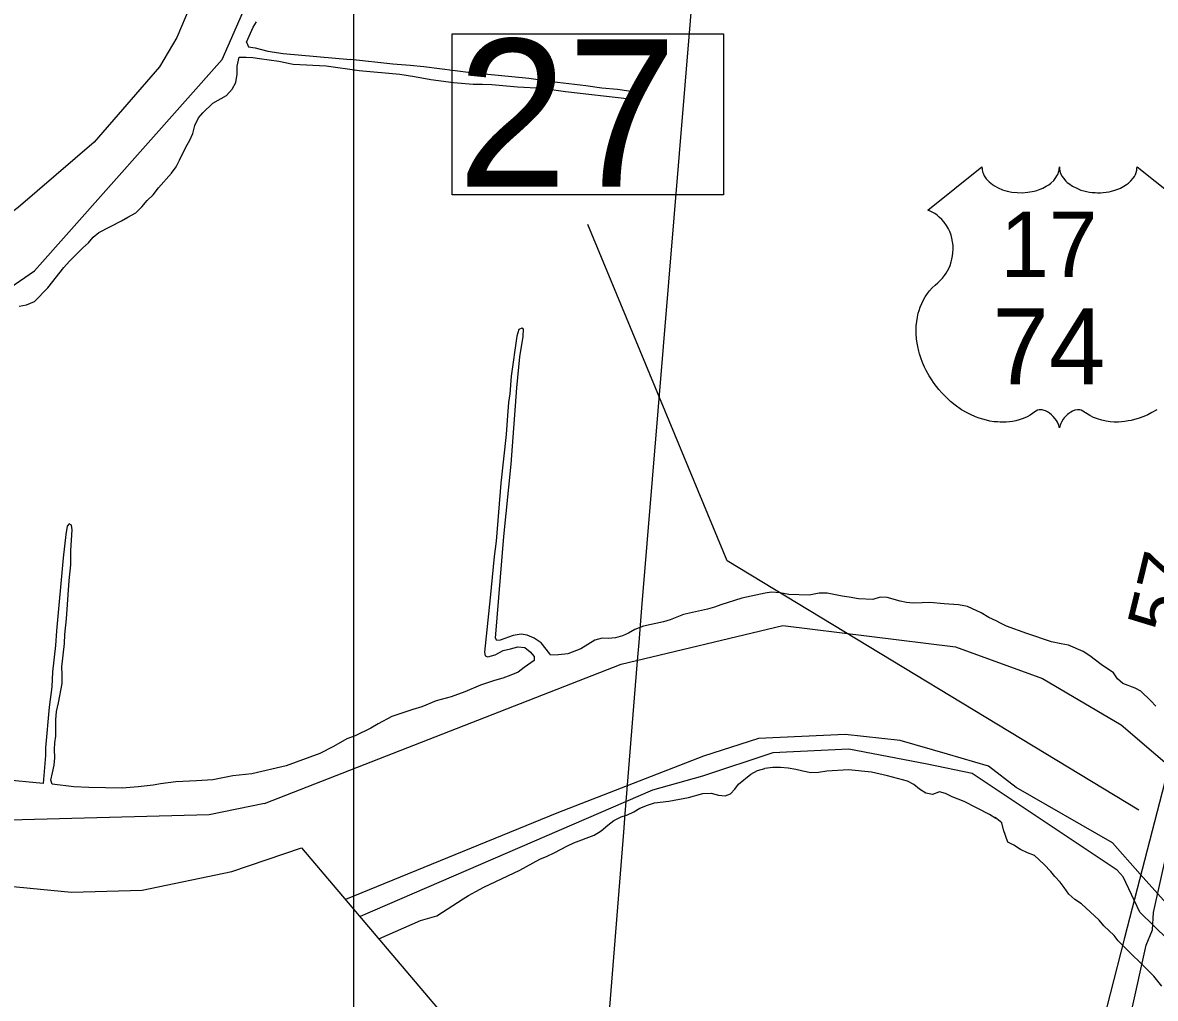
# Model space of a CAD drawing. Extents: x 2290055 to 2389491, y 66597 to 237875.
# Drawn here: x 2312342 to 2315029, y 180442 to 182758 of the extents above; entities that cross this region are included whole.
import ezdxf

# ---------------------------------------------------------------- set-up
doc = ezdxf.new("R2010")
doc.units = 0
for name, color, linetype in [('Exist Boundary Political CountyLine', 7, 'Continuous'), ('Exist Hydrographic Buffer Line', 7, 'Continuous'), ('Exist Hydrographic River Shore', 7, 'Continuous'), ('Exist Road Primary US Attributed', 7, 'Continuous'), ('Exist Road Primary US Mileage Hundredths English Label', 7, 'Continuous'), ('Exist Road Primary US Shield CELL', 7, 'Continuous'), ('Exist Road Primary US Shield Number Label', 7, 'Continuous'), ('Exist Road Primary US Structure Standard Bridge CELL', 7, 'Continuous'), ('Exist Road Primary US Structure Standard Bridge Number Label', 7, 'Continuous'), ('Exist Utilities Electrical Transmission Line', 7, 'Continuous'), ('Map Preparation Inset Cut Line', 7, 'Continuous')]:
    doc.layers.add(name, color=color, linetype=linetype)

msp = doc.modelspace()

# ---------------------------------------------------------------- linework, layer by layer
at = {"layer": 'Exist Boundary Political CountyLine'}
for points in [[(2312738.6, 182795.7), (2312707.5, 182722.4), (2312666.3, 182652.8), (2312511.3, 182474.6), (2312331.3, 182319.4), (2311958.3, 182038.6), (2311667.7, 181799), (2311602.1, 181738.4), (2311491.5, 181600), (2311403.9, 181438.4), (2311394.4, 181374), (2311397.1, 181306.1), (2311422, 181233.1), (2311456.7, 181164.4), (2311514.3, 181074.7), (2311599.9, 180984), (2311719.1, 180904.7), (2311839.9, 180833.5), (2312044.8, 180763.6), (2312252.8, 180713.8), (2312457.7, 180693.9), (2312625.5, 180698.5), (2312837.8, 180742.9), (2313003.6, 180799.5)], [(2313003.6, 180799.5), (2315382.1, 177993.9), (2314179.2, 167721.2), (2314074.7, 167198.8), (2314144.3, 166676.3), (2314579.5, 166032), (2315320.8, 164453.7), (2315408.1, 164067), (2315607.7, 162054.2)]]:
    msp.add_lwpolyline(points, dxfattribs=at)
at = {"layer": 'Exist Hydrographic Buffer Line'}
for points in [[(2312915.3, 180904.3), (2312784.2, 180877.2), (2312280.5, 180864), (2311880.3, 180937), (2311776.3, 180989.9), (2311584.2, 181167.8), (2311544.4, 181324.4), (2311632, 181579.3), (2311894.7, 181852.7), (2312106.9, 181988.1), (2312369.6, 182168.7), (2312815.4, 182670.4), (2312897.6, 182858.9), (2312941.4, 183165.6), (2312948.5, 183207.3), (2312949.4, 183290.4), (2312791, 183641.7)], [(2312915.3, 180904.3), (2313761.5, 181235.3), (2314145.5, 181326.9), (2314555.1, 181276.5), (2314761.4, 181201.1), (2314948.2, 181091.6), (2315195.3, 180879.7)], [(2315077, 180643.3), (2314993, 180736.7), (2314927.7, 180811.4), (2314699.1, 180942.1), (2314633.8, 180993.4), (2314535.8, 181021.4), (2314423.9, 181054.1), (2314293.2, 181068.1), (2314088, 181058.8), (2313957.3, 181016.8), (2313608.8, 180881.7), (2313107.8, 180676.6)], [(2314487.8, 180997.9), (2314301.8, 181033.5), (2314122.1, 181024.4), (2313954.7, 180969.5), (2313836, 180936), (2313142.1, 180636.2)], [(2315289.6, 180356.3), (2314992.6, 180646.6), (2314952.7, 180730.4), (2314938.9, 180746.5), (2314595, 180975.7), (2314487.8, 180997.9)]]:
    msp.add_lwpolyline(points, dxfattribs=at)
at = {"layer": 'Exist Hydrographic River Shore'}
for points in [[(2312872.5, 182711.3), (2312888.2, 182746.9), (2312896.5, 182759.8)], [(2312872.5, 182711.3), (2312877.7, 182701), (2312893.2, 182698.1), (2312923.2, 182690.5), (2312960, 182684.4), (2313119.7, 182670.6)], [(2312851, 182636.1), (2312851, 182654.5), (2312855.7, 182675.8)], [(2312855.7, 182675.8), (2312872.2, 182676.4), (2312887.5, 182675.5), (2312903.7, 182672.6), (2312949.7, 182666.5), (2312983.7, 182659.6), (2313061.5, 182655.9), (2313140.5, 182644.7), (2313236.5, 182635.4), (2313271.7, 182630.5), (2313310, 182623.1), (2313364, 182615.7), (2313410.5, 182612.1), (2313432.7, 182612.2), (2313455.2, 182611.1), (2313515.5, 182605.3), (2313575.5, 182602.4), (2313629.5, 182594.6), (2313782, 182576.8), (2313798.7, 182577.3), (2313802.7, 182582.5), (2313801.5, 182591.9), (2313753.5, 182599.5), (2313715.7, 182602.5), (2313678, 182608.1), (2313597.5, 182617.3), (2313542.7, 182625.6), (2313405.2, 182638.6), (2313293.5, 182653), (2313261, 182656.3), (2313220.2, 182659.3), (2313119.7, 182670.6)], [(2312333.2, 182084.9), (2312350.5, 182088.3), (2312369.5, 182096.4), (2312401.5, 182128.7), (2312439, 182176.8), (2312452.5, 182191.7), (2312484.2, 182223.7), (2312497.5, 182235.2), (2312509, 182248.7), (2312522.5, 182260.2), (2312576.5, 182287.3), (2312591.5, 182296.6), (2312610.5, 182306.4), (2312624.2, 182321), (2312636.7, 182336.2), (2312651, 182349.3), (2312663.7, 182366), (2312694.5, 182400.9), (2312705.5, 182415.6), (2312714, 182431.2), (2312729, 182462.1), (2312738.5, 182478.9), (2312745.7, 182494.9), (2312750, 182513.7), (2312759, 182532), (2312769, 182543.7), (2312792.7, 182567), (2312825.5, 182584.8), (2312838.5, 182600.2), (2312847.2, 182615.6), (2312851, 182636.1)], [(2313635.5, 181259.4), (2313613.5, 181257.2), (2313594, 181256.5), (2313592.5, 181260), (2313572.2, 181285.9), (2313555.5, 181297), (2313539, 181303.9), (2313524.5, 181306.6), (2313505.7, 181303), (2313474.7, 181292), (2313467, 181291.3), (2313464, 181297.3), (2313483.2, 181538.5), (2313501, 181709.6), (2313514.2, 181891), (2313521.2, 181964.8), (2313529.5, 182013.2), (2313530, 182030.1), (2313526.5, 182032.7), (2313518.7, 182029.9), (2313514.2, 182013.9), (2313501, 181919.2), (2313497.5, 181877.3), (2313494.5, 181856.5), (2313491.7, 181825.8), (2313489, 181780.2), (2313476, 181664.8), (2313465.2, 181527.4), (2313460.5, 181491), (2313451.2, 181393), (2313437.2, 181263.9), (2313439.2, 181255), (2313445.7, 181252.9), (2313462.5, 181257.7), (2313482, 181267.5), (2313499.5, 181271.9), (2313516.5, 181276), (2313533.2, 181274.7), (2313545.7, 181264.8), (2313555.5, 181253.4), (2313555.5, 181243.8)], [(2312435.7, 181210.7), (2312434.2, 181229), (2312440.7, 181284.3), (2312442, 181305.8), (2312445.7, 181342.7), (2312452.2, 181433.7), (2312456, 181471.4), (2312456.2, 181504.9), (2312458.7, 181554.3), (2312457.5, 181564.8), (2312452, 181568.5), (2312447.5, 181563), (2312443.7, 181543.3), (2312437.7, 181487.7), (2312421.7, 181314.4), (2312419.7, 181279.4), (2312412.5, 181216.9), (2312410.5, 181181.7), (2312404.5, 181133.4), (2312396, 181037), (2312396, 181018.1), (2312390.5, 180952.3)], [(2315030.2, 181135.3), (2315018.5, 181148.4), (2314995.2, 181170.8), (2314981.5, 181178.5), (2314952, 181189.1), (2314939.5, 181200.3), (2314930, 181214.7), (2314900.5, 181234.2), (2314873.7, 181255.3), (2314858, 181265.1), (2314823.5, 181280.2), (2314805.7, 181283.1), (2314783.2, 181288.1), (2314724.5, 181307.7), (2314676.5, 181325.3), (2314662.2, 181332.2), (2314652, 181338.3), (2314634.5, 181346.3), (2314616, 181357.4), (2314584, 181372), (2314562, 181376.1), (2314528.5, 181378.3), (2314494.5, 181381.7), (2314476, 181380.6), (2314454.5, 181380.4), (2314438.5, 181381.6), (2314424, 181384.7), (2314393, 181393.6), (2314376.5, 181394.2), (2314359, 181388.9), (2314324.7, 181390.6), (2314303, 181394.5), (2314286, 181396.5), (2314250.5, 181403.6), (2314231.5, 181403.4), (2314208, 181399.1), (2314160, 181400.5), (2314138, 181404.9), (2314118.5, 181406.1), (2314103.2, 181403.7), (2314048.2, 181391.9)], [(2314048.2, 181391.9), (2313998, 181376.2), (2313983.2, 181370.3), (2313967, 181365.8), (2313909.7, 181352.9), (2313878, 181340.4), (2313862.5, 181335.7), (2313815, 181325.4), (2313794.5, 181317.9), (2313779.5, 181308.8), (2313764.7, 181302.3), (2313748.7, 181297.9), (2313731.2, 181296.3), (2313717, 181296.7), (2313699, 181292.4), (2313666.5, 181271.7), (2313635.5, 181259.4)], [(2313555.5, 181243.8), (2313531.5, 181227.1), (2313517.5, 181216.3), (2313500, 181209), (2313481, 181202.3), (2313461, 181196.8), (2313428, 181185.2), (2313390.5, 181169.8), (2313358.5, 181157.7), (2313323.2, 181147.9), (2313289.2, 181133.8), (2313267.2, 181127.8), (2313217.7, 181111), (2313185, 181093.8), (2313168, 181083), (2313130.5, 181064.8), (2313111.2, 181058.2), (2313079.5, 181039.7), (2313046.5, 181023), (2312967, 180994.1), (2312885.2, 180974.8), (2312840, 180970.2), (2312792.5, 180960.7), (2312754.2, 180957.9), (2312704.7, 180955.7), (2312669, 180951.1), (2312651.2, 180947.8), (2312615.5, 180944), (2312578, 180941.2), (2312498.5, 180942.3), (2312462.7, 180943.8), (2312411.7, 180950)], [(2312411.7, 180950), (2312408.5, 180959.8), (2312412.7, 180977.3), (2312416, 180995.1), (2312417.7, 181012.9), (2312417.2, 181032.9), (2312417.7, 181048.8), (2312420, 181064.1), (2312420, 181102.9), (2312422.2, 181123), (2312427, 181143.4), (2312435.5, 181189), (2312435.7, 181210.7)], [(2313186.8, 180583.4), (2313285.5, 180626.8), (2313324.5, 180637.5), (2313386.5, 180678.2), (2313399.2, 180686.2), (2313417, 180695.9), (2313435.7, 180705.6), (2313521.7, 180746.3), (2313568.7, 180772.1), (2313586, 180779.3), (2313602.5, 180787.3), (2313634.2, 180804.2), (2313649.5, 180810.9), (2313697.5, 180829.5), (2313714, 180839.4), (2313730, 180853), (2313744.7, 180864), (2313761.5, 180873), (2313776.7, 180877.6), (2313792, 180884.6), (2313806.5, 180893.3), (2313824.5, 180900.8), (2313841.2, 180905.8), (2313874.7, 180910.3), (2313921.7, 180918.9), (2313955.5, 180928.3), (2313975.7, 180928.7), (2313993, 180924.3), (2314008.5, 180922.8), (2314021, 180927.2), (2314031.2, 180938.4), (2314040.2, 180950.6), (2314069.5, 180973.8), (2314085.7, 180982.5), (2314103, 180987.8)], [(2315045, 180471.2), (2315025.5, 180494.4), (2314941, 180578.7), (2314931.7, 180591.1), (2314907.5, 180613.8), (2314896.2, 180627.8), (2314854, 180666.2), (2314838.5, 180676.6), (2314824, 180689), (2314813, 180705.2), (2314803.5, 180717.5), (2314791, 180731.3), (2314781.5, 180743.3), (2314765.7, 180759.6), (2314742.5, 180780.7), (2314726, 180787.3), (2314709.7, 180795.5), (2314693.7, 180805.4), (2314679.7, 180813), (2314669, 180842.2), (2314665.2, 180858.2), (2314649.2, 180871.4), (2314650.7, 180869.1), (2314636, 180878.7), (2314576, 180909.2), (2314547.5, 180920.6), (2314531.5, 180928.3), (2314517.5, 180931.9), (2314500.7, 180926.2), (2314485, 180928.9), (2314470, 180938.4), (2314456.5, 180949.7), (2314441.5, 180957.4), (2314394, 180970.2), (2314355.5, 180979.2), (2314301.2, 180984.3), (2314249.5, 180981), (2314230.2, 180978.4), (2314212.2, 180977.6), (2314193.2, 180981), (2314176.2, 180985.5), (2314158, 180988.5), (2314140, 180990.3), (2314121.5, 180990), (2314103, 180987.8)], [(2312390.5, 180952.3), (2312291.5, 180961.6)]]:
    msp.add_lwpolyline(points, dxfattribs=at)
at = {"layer": 'Exist Road Primary US Attributed'}
msp.add_lwpolyline([(2314811.7, 178747.2), (2314847.9, 178990), (2314859, 179259.7), (2314851, 179369.3), (2314854.1, 179668.5), (2314896, 179969.4), (2314909.5, 180112.5), (2314940.7, 180260), (2314972, 180407.5), (2315007.8, 180568.5), (2315022.6, 180604.5), (2315025, 180646), (2315045.5, 180738.2), (2315052.5, 180769.7), (2315070.3, 180837.2)], dxfattribs=at)
at = {"layer": 'Exist Road Primary US Shield CELL'}
msp.add_lwpolyline([(2315032.8, 181839.1), (2315021.1, 181832.4), (2315011.2, 181827.3), (2315002.4, 181823.5), (2314991, 181819.2), (2314972, 181813.9), (2314965.1, 181812.5), (2314956.9, 181811.3), (2314949.2, 181810.5), (2314941.8, 181810), (2314931.7, 181810), (2314921.8, 181810.8), (2314912.4, 181812.2), (2314902.6, 181814.2), (2314892.3, 181817.3), (2314883, 181820.9), (2314873.6, 181825.5), (2314857.7, 181835.6), (2314853.1, 181838), (2314850.5, 181838.7), (2314844.4, 181839), (2314838.6, 181837.8), (2314832.7, 181835.4), (2314829.1, 181833.5), (2314824.3, 181830.4), (2314820.7, 181827.5), (2314816.3, 181823.3), (2314813.3, 181819.8), (2314810.9, 181817.1), (2314806.5, 181810), (2314804.9, 181806.7), (2314803.2, 181802.4), (2314801.7, 181796), (2314799.7, 181804), (2314797.3, 181809.4), (2314794.6, 181813.9), (2314791.8, 181817.9), (2314787.3, 181823.1), (2314783.3, 181827), (2314778.4, 181830.9), (2314773.2, 181834.1), (2314769.1, 181836.2), (2314765.3, 181837.6), (2314760.7, 181838.8), (2314756.9, 181839.1), (2314753.8, 181839), (2314749.5, 181838), (2314743.7, 181833.8), (2314738.1, 181830), (2314732.1, 181826.3), (2314725, 181822.5), (2314719.8, 181820.1), (2314713.5, 181817.6), (2314706.3, 181815.2), (2314698.4, 181813.2), (2314690.2, 181811.6), (2314683.1, 181810.4), (2314675.4, 181809.7), (2314668.5, 181809.5), (2314661.3, 181809.6), (2314654.5, 181810.1), (2314646.7, 181810.8), (2314637, 181812.2), (2314628.9, 181814.1), (2314620.4, 181816.4), (2314611.7, 181819.1), (2314602.4, 181822.7), (2314590.7, 181827.7), (2314582.5, 181831.9), (2314569.7, 181839.3), (2314554.7, 181849.7), (2314543.3, 181858.9), (2314535, 181866.4), (2314522.8, 181878.9), (2314515.6, 181887), (2314504.3, 181901.6), (2314497.1, 181912.2), (2314492.4, 181919.9), (2314485.6, 181932.4), (2314481.8, 181940.2), (2314477, 181951.6), (2314473.1, 181962), (2314469.9, 181971.9), (2314468.2, 181978.2), (2314465.8, 181989.2), (2314464.3, 181997), (2314462.9, 182007.8), (2314462.1, 182019.1), (2314461.9, 182029.5), (2314462.2, 182038.2), (2314463.2, 182048.3), (2314464.9, 182059), (2314466.9, 182068.2), (2314468.8, 182074.8), (2314471.5, 182082.8), (2314475.1, 182091.7), (2314479.4, 182100.2), (2314483.5, 182107.3), (2314488.6, 182114.9), (2314493.6, 182121.4), (2314500.1, 182128.5), (2314507, 182135), (2314513.2, 182140.1), (2314520.7, 182147.4), (2314524.6, 182151.8), (2314529.2, 182158), (2314532.9, 182163.7), (2314535.9, 182168.8), (2314539.8, 182176.3), (2314542.2, 182181.9), (2314545.1, 182190.6), (2314546.6, 182196.7), (2314548.1, 182204.5), (2314549.1, 182211.9), (2314549.5, 182221.1), (2314549.3, 182228.7), (2314548.3, 182237.5), (2314546.6, 182246.1), (2314544.6, 182253.5), (2314541.4, 182262), (2314538.5, 182268.2), (2314533.6, 182276.7), (2314528.1, 182284.5), (2314522.4, 182290.9), (2314516.7, 182296.6), (2314511.3, 182300.8), (2314506.1, 182304.6), (2314499.5, 182308.5), (2314493.2, 182311.6), (2314489.3, 182313.2), (2314617.9, 182415.7), (2314618.2, 182410.3), (2314619.5, 182404), (2314620.5, 182400.8), (2314623.4, 182394.5), (2314628.3, 182387.2), (2314635.1, 182379.9), (2314642.8, 182373.6), (2314647.9, 182370.3), (2314656.7, 182365.6), (2314666.6, 182361.4), (2314677.7, 182358.2), (2314689, 182355.9), (2314701.4, 182354.6), (2314713.7, 182354.3), (2314726.9, 182355.3), (2314741.5, 182358.1), (2314748.2, 182359.9), (2314755.7, 182362.5), (2314762.7, 182365.4), (2314770.4, 182369.5), (2314776.5, 182373.4), (2314781.4, 182376.9), (2314788.2, 182383.4), (2314793.6, 182390.2), (2314795.9, 182394), (2314797.9, 182397.7), (2314800.6, 182405.4), (2314801.3, 182408.8), (2314801.9, 182415.9), (2314802.3, 182410), (2314802.9, 182406.2), (2314803.9, 182402.6), (2314805.4, 182398.7), (2314808.2, 182393.2), (2314811.2, 182388.7), (2314816.9, 182381.9), (2314820.5, 182378.6), (2314823.8, 182375.9), (2314832.5, 182369.9), (2314842.7, 182364.8), (2314847.7, 182362.5), (2314852.9, 182360.7), (2314859.4, 182358.7), (2314866.2, 182357.2), (2314872.9, 182356), (2314879.7, 182355), (2314886.7, 182354.5), (2314892.4, 182354.3), (2314899.4, 182354.4), (2314905.8, 182354.8), (2314912.4, 182355.6), (2314919.7, 182356.8), (2314925.6, 182358.1), (2314933.3, 182360.1), (2314940.3, 182362.6), (2314946.5, 182365.3), (2314954.4, 182369.5), (2314960.9, 182373.5), (2314965.6, 182377.3), (2314971.2, 182382.5), (2314976.6, 182388.6), (2314979.7, 182393.1), (2314981.9, 182397.7), (2314983.9, 182402.6), (2314985.2, 182407.8), (2314985.8, 182412.2), (2314985.9, 182416.1), (2315114.5, 182313.6)], dxfattribs=at)
at = {"layer": 'Exist Road Primary US Structure Standard Bridge CELL'}
msp.add_lwpolyline([(2314789.5, 179807.9), (2314958.1, 179798.1), (2315022.4, 180180.2), (2315134.6, 180651.8), (2315348.8, 181560.7), (2315385.7, 181891.1), (2315237.7, 181890.7), (2315217.9, 181598.2), (2314955.9, 180585.9), (2314853.8, 180186.6), (2314823.4, 179980)], close=True, dxfattribs=at)
at = {"layer": 'Exist Road Primary US Structure Standard Bridge Number Label'}
msp.add_lwpolyline([(2313360.7, 182731.4), (2314004.9, 182731.4), (2314004.9, 182349), (2313360.7, 182349)], close=True, dxfattribs=at)
msp.add_lwpolyline([(2314990.2, 180888.7), (2314013.1, 181480.5), (2313682.8, 182278.7)], dxfattribs=at)
at = {"layer": 'Exist Utilities Electrical Transmission Line'}
for p, q in [((2313800.8, 181242.8), (2313804.4, 181286.6)), ((2313793.8, 181155.2), (2313800.8, 181242.8)), ((2313778.8, 180967.9), (2313793.8, 181155.2)), ((2313771.7, 180880.1), (2313778.8, 180967.9)), ((2313768.2, 180836.6), (2313771.7, 180880.1)), ((2313699.4, 179978.8), (2313768.2, 180836.6))]:
    msp.add_line(p, q, dxfattribs=at)
msp.add_lwpolyline([(2313804.4, 181286.6), (2313811, 181369.2), (2314003.3, 183689.2), (2314307.8, 187086.1)], dxfattribs=at)
at = {"layer": 'Map Preparation Inset Cut Line'}
msp.add_lwpolyline([(2374088.6, 192135.8), (2313126.6, 192135.8), (2313126.6, 149726.2), (2353934.7, 149726.2), (2375181.1, 184193.5), (2380407.7, 192135.8)], close=True, dxfattribs=at)

# ---------------------------------------------------------------- texts
at = {"layer": 'Exist Road Primary US Mileage Hundredths English Label'}
msp.add_text('.57', height=125, rotation=76.291, dxfattribs=at).set_placement((2315071.7, 181255))
at = {"layer": 'Exist Road Primary US Shield Number Label'}
for s, height, p in [('17', 155, (2314661.7, 182154.3)), ('74', 180, (2314643, 181899.5))]:
    msp.add_text(s, height=height, dxfattribs=at).set_placement(p)
at = {"layer": 'Exist Road Primary US Structure Standard Bridge Number Label'}
msp.add_text('27', height=350, dxfattribs=at).set_placement((2313373.3, 182368.8))

doc.saveas('drawing.dxf')
